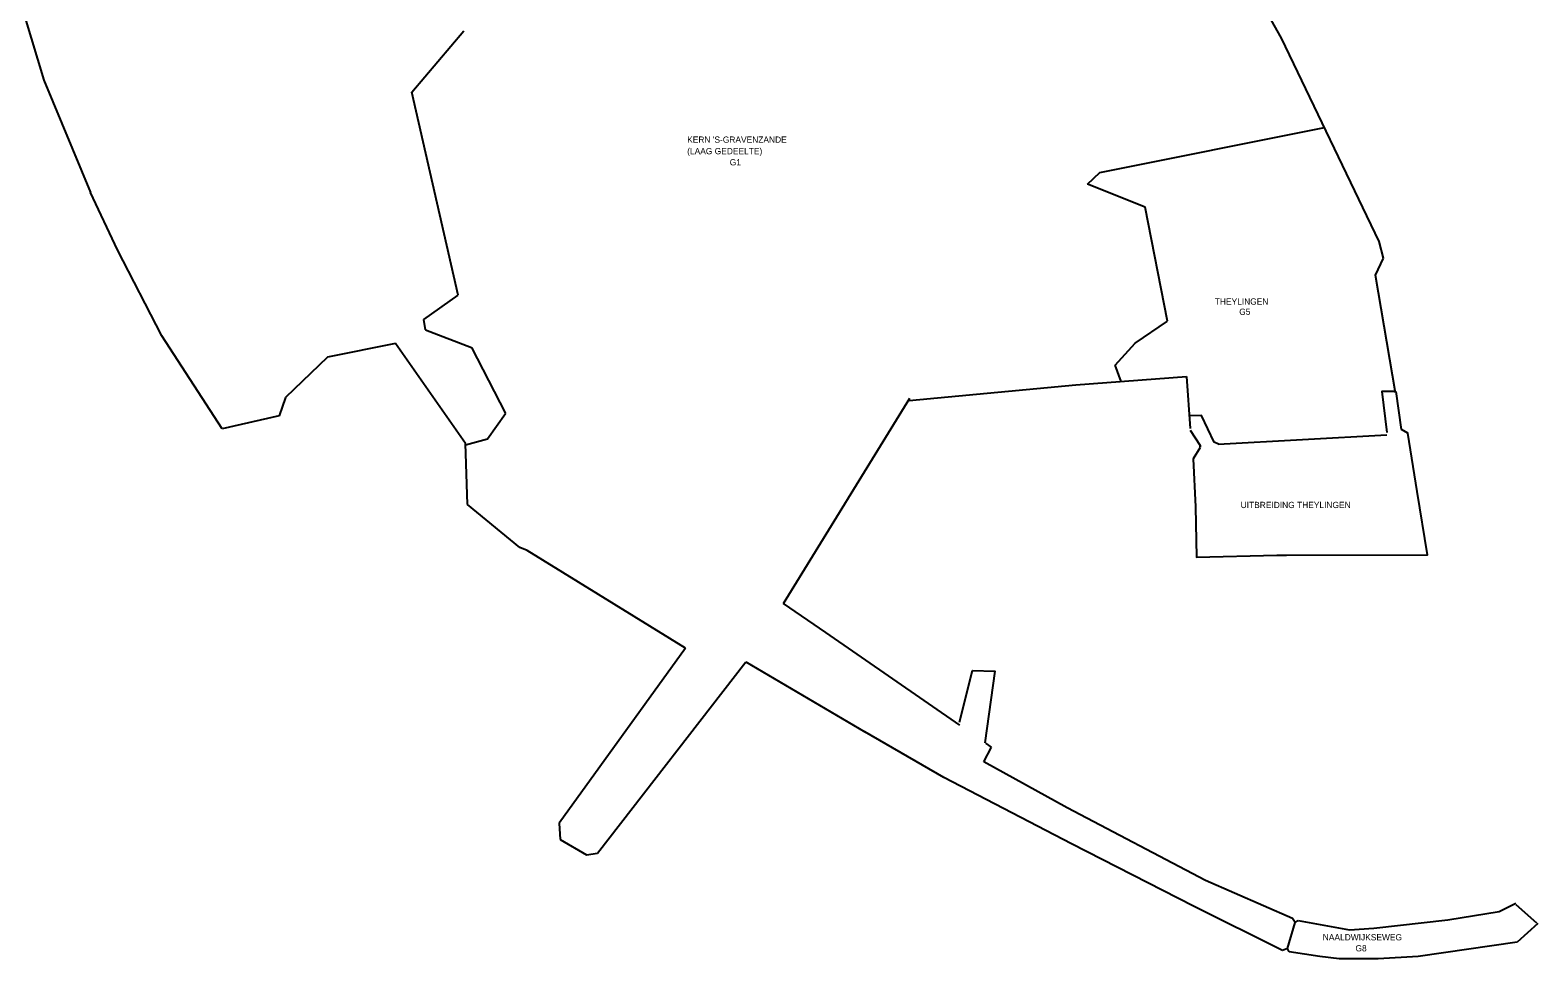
# Model space of a CAD drawing. Extents: x 69068 to 80855, y 440023 to 451362.
# Drawn here: x 70305 to 72468, y 445127 to 446460 of the extents above; entities that cross this region are included whole.
import ezdxf

# ---------------------------------------------------------------- set-up
doc = ezdxf.new("R2010")
doc.units = 0
for name, color, linetype in [('Bemalingsgebiednummer', 7, 'Continuous'), ('Bemalingsgebiedsgrens', 7, 'Continuous'), ('RIO_Leidingen', 7, 'Continuous'), ('Scheiding', 7, 'Continuous')]:
    doc.layers.add(name, color=color, linetype=linetype)

msp = doc.modelspace()

# ---------------------------------------------------------------- linework, layer by layer
at = {"layer": 'Bemalingsgebiedsgrens'}
for p, q in [((70218.1, 446743.2), (70325.1, 446387.7)), ((72100, 446448.1), (72019.3, 446592.1)), ((72240.3, 446156.3), (72100, 446448.1)), ((70325.1, 446387.7), (70391.8, 446226.7)), ((71839.4, 446255.5), (72161.6, 446320)), ((71821.9, 446238.8), (71839.4, 446255.5)), ((70430.4, 446144.4), (70391.8, 446226.7)), ((71904.4, 446205.4), (71821.9, 446238.8)), ((71936.8, 446042.1), (71904.4, 446205.4)), ((72246.5, 446132.6), (72240.3, 446156.3)), ((70494.4, 446021), (70430.4, 446144.4)), ((72235.1, 446108), (72246.5, 446132.6)), ((72263.5, 445939.2), (72235.1, 446108)), ((71890.3, 446010.5), (71936.8, 446042.1)), ((70580.9, 445887.3), (70494.4, 446021)), ((70829.1, 446009.8), (70731.7, 445990.5)), ((70929.6, 445866.5), (70829.1, 446009.8)), ((71861.4, 445978.9), (71890.3, 446010.5)), ((70731.7, 445990.5), (70671.8, 445932.6)), ((71805.1, 445950.6), (71963.9, 445962.6)), ((71869.9, 445955.5), (71861.4, 445978.9)), ((71963.9, 445962.6), (71968.9, 445888.2)), ((71566.1, 445928.4), (71805.1, 445950.6)), ((72272.1, 445886.4), (72264.4, 445941)), ((70671.8, 445932.6), (70662.4, 445906)), ((71385.6, 445636.7), (71566.8, 445931.5)), ((70662.4, 445906), (70580.9, 445887.3)), ((71968.9, 445885.6), (71983.6, 445863.7)), ((72009.2, 445865.6), (72251.3, 445878.9)), ((70932.7, 445779.1), (70929.6, 445866.5)), ((71982.2, 445862.8), (71984.9, 445863)), ((71007.8, 445717.1), (70932.7, 445779.1)), ((71018, 445713.1), (71007.8, 445717.1)), ((71245.2, 445572.9), (71018, 445713.1)), ((71446.5, 445595.4), (71385.6, 445636.7)), ((71638.6, 445462.5), (71446.5, 445595.4)), ((71245.2, 445572.9), (71064.1, 445321.6)), ((71118.9, 445278.7), (71331.7, 445553.3)), ((71331.7, 445553.3), (71502.6, 445452.7)), ((71615.8, 445387.2), (71502.6, 445452.7)), ((71673.4, 445409.8), (71684.1, 445430.9)), ((71684.1, 445430.9), (71675.8, 445436.7)), ((71792.6, 445343.5), (71673.4, 445409.8)), ((71798.7, 445291.9), (71615.8, 445387.2)), ((71991.2, 445239.4), (71792.6, 445343.5)), ((71064.1, 445321.6), (71065.6, 445298.3)), ((71065.6, 445298.3), (71103.1, 445276.4)), ((71974.1, 445202.4), (71798.7, 445291.9)), ((71103.1, 445276.4), (71118.9, 445278.7)), ((72116.1, 445185), (71991.2, 445239.4)), ((72412.4, 445195.1), (72436, 445206.8)), ((72436.4, 445205.2), (72465.6, 445178.5)), ((72101.7, 445139), (71974.1, 445202.4)), ((72119.6, 445179.1), (72116.1, 445185)), ((72119.6, 445179.1), (72123.8, 445182)), ((72123.8, 445182), (72197.4, 445168.5)), ((72232.6, 445171.2), (72338.8, 445182.9)), ((72338.8, 445182.9), (72412.4, 445195.1)), ((72108.6, 445142.1), (72119.6, 445179.1)), ((72197.4, 445168.5), (72232.6, 445171.2)), ((72467.8, 445177.7), (72438.2, 445151)), ((72108.6, 445142.1), (72101.7, 445139)), ((72111.3, 445137.3), (72108.6, 445142.1)), ((72438.2, 445151), (72296.2, 445130.5)), ((72154.9, 445130.2), (72111.3, 445137.3)), ((72183, 445127.2), (72154.9, 445130.2)), ((72238.6, 445127), (72183, 445127.2)), ((72296.2, 445130.5), (72238.6, 445127))]:
    msp.add_line(p, q, dxfattribs=at)
for points in [[(72263.3, 445941.2), (72243.8, 445941.1), (72251, 445882.4)], [(72009.6, 445865.4), (72003.6, 445868.5), (71985.4, 445906.8), (71967.2, 445906.3)], [(71983.5, 445860.8), (71973.5, 445844.5), (71976.6, 445775.5), (71978, 445703.4), (72093.2, 445706.1), (72107.3, 445706.1), (72309.3, 445706.8), (72294.6, 445797.6), (72281.5, 445881.1), (72272.1, 445886.4)], [(71638.1, 445466.6), (71657.1, 445540.9), (71688.8, 445539.8), (71674.5, 445436.8)]]:
    msp.add_lwpolyline(points, dxfattribs=at)
at = {"layer": 'Scheiding'}
for p, q in [((70852.8, 446370.7), (70927.4, 446458.7)), ((70919.1, 446079.2), (70852.8, 446370.7)), ((70870.2, 446044.2), (70919.1, 446079.2)), ((70872.4, 446029.7), (70870.2, 446044.2)), ((70872.4, 446029.7), (70938.4, 446004)), ((70938.4, 446004), (70986.9, 445909.5)), ((70961.2, 445873.4), (70986.9, 445909.5)), ((70929.7, 445864.5), (70961.2, 445873.4))]:
    msp.add_line(p, q, dxfattribs=at)

# ---------------------------------------------------------------- texts
at = {"layer": 'Bemalingsgebiednummer'}
for s, p in [('G1', (71308.7, 446265.5)), ('G5', (72039.5, 446051)), ('G8', (72206.2, 445137.7))]:
    msp.add_text(s, height=9, dxfattribs=at).set_placement(p)
at = {"layer": 'RIO_Leidingen'}
for s, p in [("KERN 'S-GRAVENZANDE", (71247.7, 446298)), ('(LAAG GEDEELTE)', (71247.7, 446281.5)), ('THEYLINGEN', (72004.4, 446065.7)), ('UITBREIDING THEYLINGEN', (72041.5, 445773.8)), ('NAALDWIJKSEWEG', (72159.3, 445153.5))]:
    msp.add_text(s, height=9, dxfattribs=at).set_placement(p)

doc.saveas('drawing.dxf')
